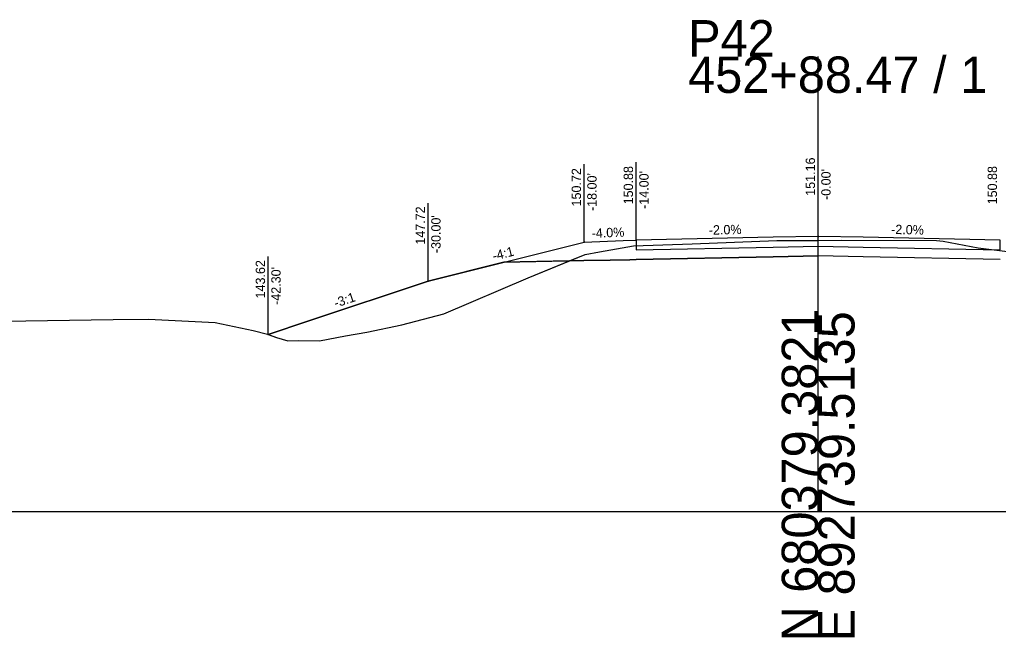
# Model space of a CAD drawing. Extents: x -26 to 4403, y -13 to 9578.
# Drawn here: x 188.6 to 263.9, y 1490.3 to 1537.8 of the extents above; entities that cross this region are included whole.
import ezdxf

# ---------------------------------------------------------------- set-up
doc = ezdxf.new("R2010")
doc.units = 0
for name, color, linetype in [('_CIVIL_CONSTRUCTION', 7, 'Continuous'), ('CONST_DCH', 7, 'Continuous'), ('CONST_LV3', 7, 'Continuous'), ('DTM_CORRIDOR', 7, 'Continuous'), ('DTM_TEMP_DROP', 7, 'Continuous'), ('DTM_X_GROUND', 7, 'Continuous'), ('SLOPE_STAKES_FILL', 7, 'Continuous'), ('XS_CELL', 7, 'Continuous'), ('XS_M_SHAPES_EARTHWORK', 7, 'Continuous'), ('XS_P_ASPHALT', 7, 'Continuous'), ('XS_P_GROUND', 7, 'Continuous'), ('XS_P_SHOULDER', 7, 'Continuous'), ('XS_P_SUBGRADE_GRANULAR', 7, 'Continuous'), ('XS_P_TX_CLEARZONE', 7, 'Continuous'), ('XS_P_TX_FS_BS', 7, 'Continuous')]:
    doc.layers.add(name, color=color, linetype=linetype)

msp = doc.modelspace()

# ---------------------------------------------------------------- linework, layer by layer
at = {"layer": 'CONST_LV3'}
msp.add_lwpolyline([(220, 1517.718), (224.383, 1518.814), (225.826, 1519.175)], dxfattribs=at)
at = {"layer": 'DTM_X_GROUND'}
msp.add_lwpolyline([(140.312, 1513.929), (195.761, 1514.758), (198.481, 1514.794), (203.63, 1514.547), (206.547, 1513.91), (207.651, 1513.635), (208.333, 1513.375), (209.208, 1513.138), (210.005, 1513.155), (211.636, 1513.116), (213.631, 1513.518), (215.277, 1513.794), (217.965, 1514.361), (221.201, 1515.199), (227.695, 1517.973), (232.073, 1519.762), (233.181, 1519.982), (235.785, 1520.428), (240.298, 1520.586), (246.827, 1520.855), (247.748, 1520.85), (250.02, 1520.854), (251.773, 1520.861), (259.098, 1520.852), (259.611, 1520.806), (261.767, 1520.382), (262.308, 1520.28), (267.608, 1519.607)], dxfattribs=at)
at = {"layer": 'XS_CELL'}
for p, q in [((250, 1500), (250, 1535)), ((0, 1500), (250, 1500)), ((250, 1500), (400, 1500))]:
    msp.add_line(p, q, dxfattribs=at)
at = {"layer": 'XS_M_SHAPES_EARTHWORK'}
msp.add_lwpolyline([(264, 1519.378), (253.468, 1519.589), (250, 1519.658), (246.532, 1519.589), (236, 1519.378), (235.505, 1519.369), (234, 1519.338), (231.975, 1519.298), (230.884, 1519.276), (232.073, 1519.762), (233.181, 1519.982), (235.785, 1520.428), (240.298, 1520.586), (246.827, 1520.855), (247.748, 1520.85), (250.02, 1520.854), (251.773, 1520.861), (259.098, 1520.852), (259.611, 1520.806), (261.767, 1520.382), (262.308, 1520.28), (267.608, 1519.607)], dxfattribs=at)
msp.add_lwpolyline([(207.696, 1513.618), (208.333, 1513.375), (209.208, 1513.138), (210.005, 1513.155), (211.636, 1513.116), (213.631, 1513.518), (215.277, 1513.794), (217.965, 1514.361), (221.201, 1515.199), (227.695, 1517.973), (230.884, 1519.276), (225.826, 1519.175), (220, 1517.718), (210.749, 1514.635)], close=True, dxfattribs=at)
at = {"layer": 'XS_P_ASPHALT'}
msp.add_lwpolyline([(246.532, 1521.089), (236, 1520.878), (236, 1520.693), (236, 1520.128), (246.532, 1520.339), (250, 1520.408), (253.468, 1520.339), (264, 1520.128), (264, 1520.693), (264, 1520.878), (253.468, 1521.089), (250, 1521.158), (246.532, 1521.089)], dxfattribs=at)
at = {"layer": 'XS_P_GROUND'}
msp.add_lwpolyline([(207.696, 1513.618), (210.749, 1514.635), (220, 1517.718), (229.027, 1519.975), (232, 1520.718)], dxfattribs=at)
at = {"layer": 'XS_P_SHOULDER'}
msp.add_lwpolyline([(232, 1520.718), (235.009, 1520.839), (236, 1520.878)], dxfattribs=at)
at = {"layer": 'XS_P_SUBGRADE_GRANULAR'}
for points in [[(236, 1519.378), (246.532, 1519.589), (250, 1519.658)], [(264, 1519.378), (253.468, 1519.589), (250, 1519.658)], [(225.826, 1519.175), (231.975, 1519.298), (234, 1519.338), (235.505, 1519.369), (236, 1519.378)]]:
    msp.add_lwpolyline(points, dxfattribs=at)
at = {"layer": 'XS_P_TX_CLEARZONE'}
for p, q in [((250, 1521.158), (250, 1527.158)), ((250, 1521.158), (250, 1527.158)), ((250, 1521.158), (250, 1527.158)), ((250, 1521.158), (250, 1527.158)), ((250, 1521.158), (250, 1527.158)), ((250, 1521.158), (250, 1527.158)), ((232, 1520.718), (232, 1526.718)), ((232, 1520.718), (232, 1526.718)), ((232, 1520.718), (232, 1526.718)), ((232, 1520.718), (232, 1526.718)), ((232, 1520.718), (232, 1526.718)), ((232, 1520.718), (232, 1526.718)), ((236, 1520.878), (236, 1526.878)), ((236, 1520.878), (236, 1526.878)), ((236, 1520.878), (236, 1526.878)), ((236, 1520.878), (236, 1526.878)), ((236, 1520.878), (236, 1526.878)), ((236, 1520.878), (236, 1526.878)), ((220, 1517.718), (220, 1523.718)), ((220, 1517.718), (220, 1523.718)), ((220, 1517.718), (220, 1523.718)), ((220, 1517.718), (220, 1523.718)), ((220, 1517.718), (220, 1523.718)), ((220, 1517.718), (220, 1523.718)), ((207.696, 1513.618), (207.696, 1519.618)), ((207.696, 1513.618), (207.696, 1519.618)), ((207.696, 1513.618), (207.696, 1519.618)), ((207.696, 1513.618), (207.696, 1519.618)), ((207.696, 1513.618), (207.696, 1519.618)), ((207.696, 1513.618), (207.696, 1519.618))]:
    msp.add_line(p, q, dxfattribs=at)

# ---------------------------------------------------------------- texts
at = {"layer": '_CIVIL_CONSTRUCTION'}
for p in [(235.961, 1520.818), (249.961, 1521.098)]:
    msp.add_text('X', height=0.12, dxfattribs=at).set_placement(p)
at = {"layer": 'CONST_DCH'}
msp.add_text('X', height=0.12, dxfattribs=at).set_placement((207.657, 1513.558))
at = {"layer": 'DTM_CORRIDOR'}
msp.add_text('X', height=0.12, dxfattribs=at).set_placement((207.657, 1513.558))
at = {"layer": 'DTM_TEMP_DROP'}
msp.add_text('X', height=0.12, dxfattribs=at).set_placement((231.961, 1520.658))
at = {"layer": 'SLOPE_STAKES_FILL'}
msp.add_text('X', height=0.12, dxfattribs=at).set_placement((219.961, 1517.658))
at = {"layer": 'XS_CELL'}
for s, p in [('P42', (240, 1535)), ('452+88.47 / 1', (240, 1532.2))]:
    msp.add_text(s, height=2.8, dxfattribs=at).set_placement(p)
for s, p in [('N 680379.3821', (250, 1490)), ('E 892739.5135', (252.8, 1490))]:
    msp.add_text(s, height=2.8, rotation=90, dxfattribs=at).set_placement(p)
at = {"layer": 'XS_P_TX_CLEARZONE'}
for s, p in [('151.16', (249.76, 1524.286)), ('151.16', (249.76, 1524.286)), ('151.16', (249.76, 1524.286)), ('151.16', (249.76, 1524.286)), ('151.16', (249.76, 1524.286)), ('151.16', (249.76, 1524.286)), ('150.72', (231.76, 1523.466)), ('150.72', (231.76, 1523.466)), ('150.72', (231.76, 1523.466)), ('150.72', (231.76, 1523.466)), ('150.72', (231.76, 1523.466)), ('150.72', (231.76, 1523.466)), ('150.88', (235.76, 1523.626)), ('150.88', (235.76, 1523.626)), ('150.88', (235.76, 1523.626)), ('150.88', (235.76, 1523.626)), ('150.88', (235.76, 1523.626)), ('150.88', (235.76, 1523.626)), ("-0.00'", (250.96, 1523.963)), ("-0.00'", (250.96, 1523.963)), ("-0.00'", (250.96, 1523.963)), ("-0.00'", (250.96, 1523.963)), ("-0.00'", (250.96, 1523.963)), ("-0.00'", (250.96, 1523.963)), ('150.88', (263.76, 1523.626)), ('150.88', (263.76, 1523.626)), ('150.88', (263.76, 1523.626)), ("-18.00'", (232.96, 1523.115)), ("-18.00'", (232.96, 1523.115)), ("-18.00'", (232.96, 1523.115)), ("-18.00'", (232.96, 1523.115)), ("-18.00'", (232.96, 1523.115)), ("-18.00'", (232.96, 1523.115)), ("-14.00'", (236.96, 1523.275)), ("-14.00'", (236.96, 1523.275)), ("-14.00'", (236.96, 1523.275)), ("-14.00'", (236.96, 1523.275)), ("-14.00'", (236.96, 1523.275)), ("-14.00'", (236.96, 1523.275)), ('147.72', (219.76, 1520.523)), ('147.72', (219.76, 1520.523)), ('147.72', (219.76, 1520.523)), ('147.72', (219.76, 1520.523)), ('147.72', (219.76, 1520.523)), ('147.72', (219.76, 1520.523)), ("-30.00'", (220.96, 1519.876)), ("-30.00'", (220.96, 1519.876)), ("-30.00'", (220.96, 1519.876)), ("-30.00'", (220.96, 1519.876)), ("-30.00'", (220.96, 1519.876)), ("-30.00'", (220.96, 1519.876)), ('143.62', (207.456, 1516.388)), ('143.62', (207.456, 1516.388)), ('143.62', (207.456, 1516.388)), ('143.62', (207.456, 1516.388)), ('143.62', (207.456, 1516.388)), ('143.62', (207.456, 1516.388)), ("-42.30'", (208.656, 1515.889)), ("-42.30'", (208.656, 1515.889)), ("-42.30'", (208.656, 1515.889)), ("-42.30'", (208.656, 1515.889)), ("-42.30'", (208.656, 1515.889)), ("-42.30'", (208.656, 1515.889))]:
    msp.add_text(s, height=0.72, rotation=90, dxfattribs=at).set_placement(p)
at = {"layer": 'XS_P_TX_FS_BS'}
for s, rotation, p in [('-4.0%', 2.29061, (232.592, 1521.042)), ('-4.0%', 2.29061, (232.592, 1521.042)), ('-4.0%', 2.29061, (232.592, 1521.042)), ('-2.0%', 1.14576, (241.598, 1521.291)), ('-2.0%', 1.14576, (241.598, 1521.291)), ('-2.0%', 1.14576, (241.598, 1521.291)), ('-2.0%', 358.85424, (255.61, 1521.346)), ('-2.0%', 358.85424, (255.61, 1521.346)), ('-2.0%', 358.85424, (255.61, 1521.346)), ('-4:1', 14.03624, (225.047, 1519.29)), ('-4:1', 14.03624, (225.047, 1519.29)), ('-4:1', 14.03624, (225.047, 1519.29)), ('-3:1', 18.43323, (212.893, 1515.666)), ('-3:1', 18.43323, (212.893, 1515.666)), ('-3:1', 18.43323, (212.893, 1515.666))]:
    msp.add_text(s, height=0.72, rotation=rotation, dxfattribs=at).set_placement(p)

doc.saveas('drawing.dxf')
